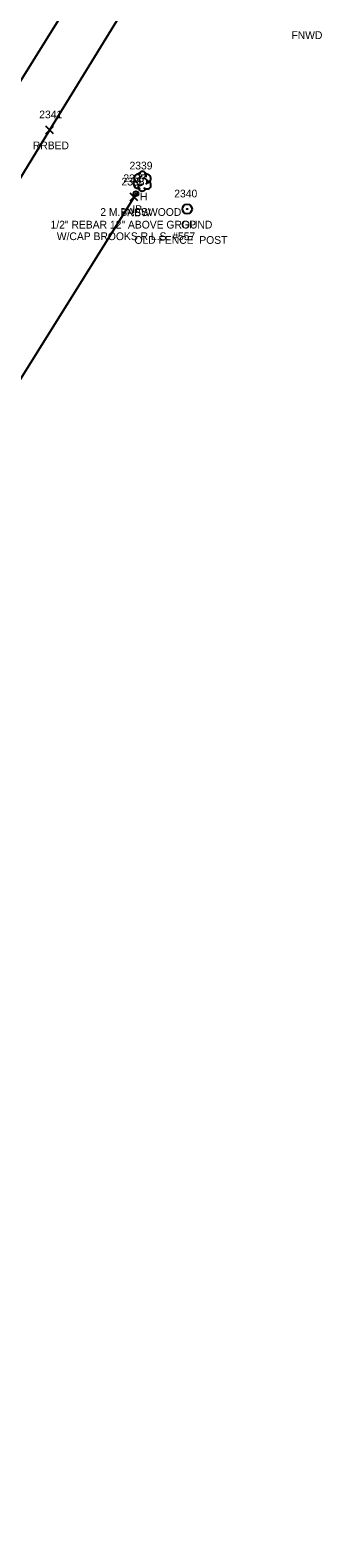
# Model space of a CAD drawing. Extents: x 1508122 to 1515053, y 865012 to 875267.
# Drawn here: x 1513963.5 to 1514039, y 873540.6 to 873930.3 of the extents above; entities that cross this region are included whole.
import ezdxf

# ---------------------------------------------------------------- set-up
doc = ezdxf.new("R2010")
doc.units = 0
for name, color, linetype in [('L_A', 7, 'Continuous'), ('L_C', 7, 'Continuous'), ('L_I', 7, 'Continuous'), ('L_TIC', 7, 'Continuous'), ('LFNC', 7, 'Continuous'), ('LTD', 7, 'Continuous'), ('M_A', 7, 'Continuous'), ('M_C', 7, 'Continuous'), ('M_I', 7, 'Continuous'), ('MPIR', 7, 'Continuous'), ('R_A', 7, 'Continuous'), ('R_C', 7, 'Continuous'), ('R_I', 7, 'Continuous'), ('R_TIC', 7, 'Continuous'), ('RGP', 7, 'Continuous'), ('RRB', 7, 'Continuous')]:
    doc.layers.add(name, color=color, linetype=linetype)

msp = doc.modelspace()

# ---------------------------------------------------------------- linework, layer by layer
at = {"layer": 'L_TIC'}
for points in [[(1513989.41, 873886.15), (1513991.41, 873888.15)], [(1513991.41, 873886.15), (1513989.41, 873888.15)]]:
    msp.add_lwpolyline(points, dxfattribs=at)
at = {"layer": 'LFNC'}
msp.add_lwpolyline([(1513883.96, 873715.43), (1513940.11, 873806.81), (1513990.41, 873887.15)], dxfattribs=at)
at = {"layer": 'LTD'}
msp.add_line((1513992.48, 873891.29), (1513992.48, 873891.29), dxfattribs=at)
msp.add_line((1513992.48, 873891.29), (1513992.48, 873891.29), dxfattribs=at)
msp.add_arc((1513992.53, 873892.72), 1.05, 335.5272, 180.9563, dxfattribs=at)
for centre, major_axis, ratio, start_param, end_param in [((1513991.4, 873890.58), (0.58, -1.04), 0.959034, 3.141593, 6.283185), ((1513991.69, 873891.95), (1.21, -0.51), 0.895232, 1.570796, 4.712389), ((1513992.02, 873890.54), (-0.625, -0.083), 0.423636, 0, 3.141593), ((1513992.27, 873891.75), (-0.208, -0.792), 0.645439, 3.141593, 6.283185), ((1513992.98, 873891.12), (-0.5, 0.667), 0.989748, 3.141593, 6.283185), ((1513993.48, 873890.45), (-1.09, 0.79), 0.841452, 1.570796, 4.712389), ((1513993.52, 873891.87), (-1.14, -0.48), 0.949671, 1.570796, 4.712389), ((1513992.48, 873889.79), (0.26, 1.06), 0.942809, 1.570796, 4.712389)]:
    msp.add_ellipse(centre, major_axis=major_axis, ratio=ratio, start_param=start_param, end_param=end_param, dxfattribs=at)
at = {"layer": 'MPIR'}
for radius in [0.625, 0.0833]:
    msp.add_circle((1513990.9, 873888.03), radius, dxfattribs=at)
at = {"layer": 'R_TIC'}
for points in [[(1513967.56, 873903.51), (1513969.56, 873905.51)], [(1513969.56, 873903.51), (1513967.56, 873905.51)]]:
    msp.add_lwpolyline(points, dxfattribs=at)
at = {"layer": 'RGP'}
msp.add_line((1514004.16, 873884.07), (1514004.16, 873884.07), dxfattribs=at)
for radius in [1.25, 0.0833]:
    msp.add_circle((1514004.16, 873884.07), radius, dxfattribs=at)
at = {"layer": 'RRB'}
for points in [[(1513228.31, 872677.99), (1513247.91, 872725.05), (1513270.86, 872775.34), (1513289.12, 872813.81), (1513319.1, 872873.87), (1513347.47, 872925.52), (1513374.77, 872971.44), (1513393.49, 873000.11), (1513437.27, 873071.02), (1513458.13, 873103.89), (1513504.32, 873179.38), (1513525.85, 873213.8), (1513574, 873293.73), (1513619.17, 873366.93), (1513650.95, 873417.63), (1513697.43, 873492.91), (1513723.07, 873532.74), (1513749.97, 873575.84), (1513797.76, 873652.14), (1513828.99, 873702.68), (1513841.18, 873722.67), (1513905.39, 873826.67), (1513957.69, 873911.9), (1513997.47, 873975.73)], [(1513240.34, 872672.59), (1513259.24, 872718.12), (1513282.12, 872769.92), (1513300.61, 872809.77), (1513331.29, 872869.64), (1513358.47, 872918.38), (1513387.89, 872964.97), (1513404.26, 872991.91), (1513448.93, 873064.4), (1513469.17, 873096.67), (1513514.98, 873172.69), (1513538.39, 873208.28), (1513585.22, 873287.66), (1513630.12, 873359.27), (1513661.28, 873410.15), (1513709.31, 873487.04), (1513733.32, 873526.23), (1513760.83, 873569.62), (1513809.55, 873645.89), (1513841.33, 873697.41), (1513850.37, 873716.18), (1513916.81, 873819.88), (1513968.56, 873904.51), (1514007.95, 873968.59)]]:
    msp.add_lwpolyline(points, dxfattribs=at)

# ---------------------------------------------------------------- texts
at = {"layer": 'L_A'}
for s, p in [('FNWD', (1514031.13, 873928.01)), ('H', (1513991.92, 873886.29)), ('FNBW', (1513986.88, 873882.15))]:
    msp.add_text(s, height=2, dxfattribs=at).set_placement(p)
at = {"layer": 'L_C'}
msp.add_text('2 M.BASSWOOD', height=2, dxfattribs=at).set_placement((1513981.67, 873882.29))
at = {"layer": 'L_I'}
for s, p in [('2339', (1513989.22, 873894.29)), ('2338', (1513987.15, 873890.15))]:
    msp.add_text(s, height=2, dxfattribs=at).set_placement(p)
at = {"layer": 'M_A'}
msp.add_text('IP', height=2, dxfattribs=at).set_placement((1513989.94, 873883.03))
at = {"layer": 'M_C'}
for s, p in [('1/2" REBAR 12" ABOVE GROUND', (1513968.79, 873879.03)), ('W/CAP BROOKS R.L.S. #557', (1513970.41, 873876.03))]:
    msp.add_text(s, height=2, dxfattribs=at).set_placement(p)
at = {"layer": 'M_I'}
msp.add_text('2337', height=2, dxfattribs=at).set_placement((1513987.64, 873891.03))
at = {"layer": 'R_A'}
for s, p in [('RRBED', (1513964.2, 873899.51)), ('GP', (1514002.59, 873879.07))]:
    msp.add_text(s, height=2, dxfattribs=at).set_placement(p)
at = {"layer": 'R_C'}
msp.add_text('OLD FENCE  POST', height=2, dxfattribs=at).set_placement((1513990.5, 873875.07))
at = {"layer": 'R_I'}
for s, p in [('2341', (1513965.86, 873907.51)), ('2340', (1514000.81, 873887.07))]:
    msp.add_text(s, height=2, dxfattribs=at).set_placement(p)

doc.saveas('drawing.dxf')
